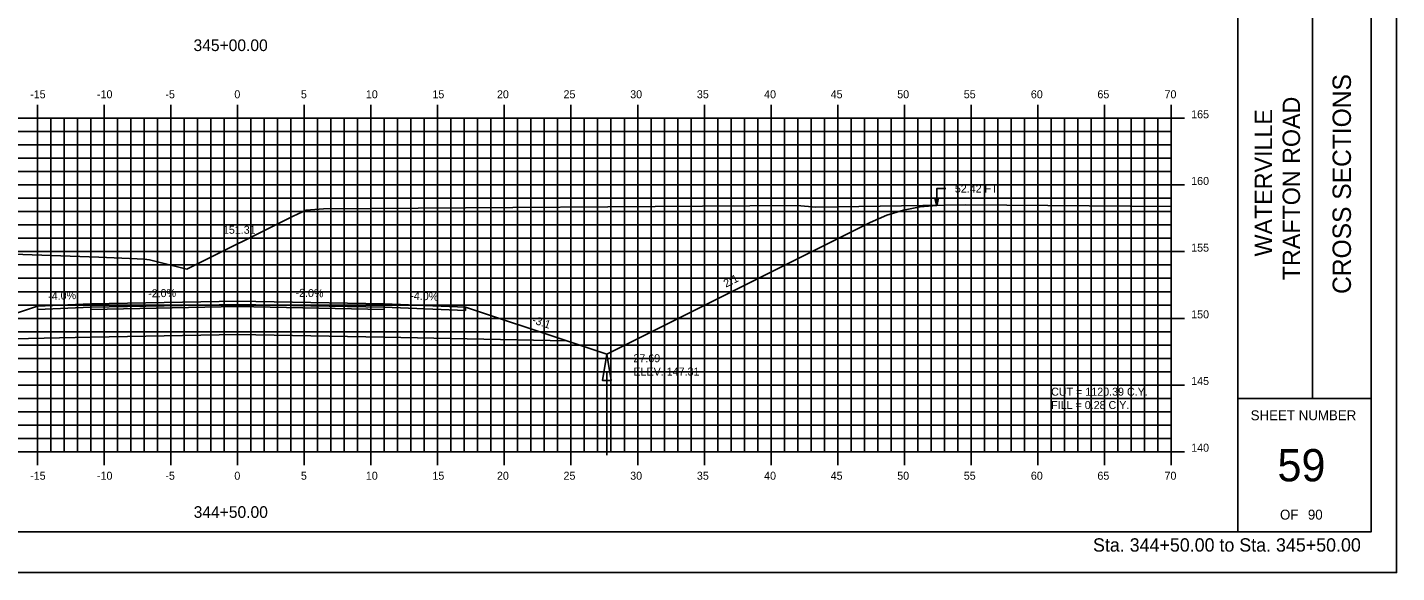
# Model space of a CAD drawing. Extents: x 1143642 to 1143812, y 608981 to 609091.
# Drawn here: x 1143709.1 to 1143811.7, y 608981.3 to 609022.2 of the extents above; entities that cross this region are included whole.
import ezdxf

# ---------------------------------------------------------------- set-up
doc = ezdxf.new("R2010")
doc.units = 0
for name, color, linetype in [('ANNOTATION', 7, 'Continuous'), ('BORDER', 7, 'Continuous'), ('D_Drainage_Ditch_Line', 7, 'Continuous'), ('D_Roadway_Centerline', 7, 'Continuous'), ('D_Roadway_Centerline_Text', 7, 'Continuous'), ('D_Roadway_Edge_Shoulder', 7, 'Continuous'), ('D_Roadway_Edge_TW', 7, 'Continuous'), ('D_Roadway_Pavement', 7, 'Continuous'), ('D_Roadway_SlopeLines', 7, 'Continuous'), ('D_Roadway_SubGrade', 7, 'Continuous'), ('D_Text_Standard', 7, 'Continuous'), ('H_V ANNOTATION', 7, 'Continuous'), ('HIGHWAY_TITLE', 7, 'Continuous'), ('MAJOR', 7, 'Continuous'), ('MINOR', 7, 'Continuous'), ('PLOT BOUNDARY', 7, 'Continuous'), ('S_Roadway_Centerline', 7, 'Continuous')]:
    doc.layers.add(name, color=color, linetype=linetype)

msp = doc.modelspace()

# ---------------------------------------------------------------- linework, layer by layer
msp.add_lwpolyline([(1143684.25, 609004.24), (1143685.5, 609004), (1143686.75, 609003.65), (1143688, 609003.19), (1143689.25, 609002.62), (1143699.11, 608997.69), (1143702.11, 608998.69), (1143709.84, 609001.26), (1143709.84, 609001.26), (1143713.84, 609001.42), (1143724.84, 609001.64), (1143735.84, 609001.42), (1143741.93, 609001.18), (1143749.52, 608998.65), (1143752.52, 608997.65), (1143772.26, 609007.52), (1143773.51, 609008.07), (1143774.76, 609008.46), (1143776.01, 609008.71), (1143777.26, 609008.8)])
at = {"layer": 'BORDER'}
for p, q in [((1143799.84, 608984.34), (1143799.84, 609089.34)), ((1143805.43, 608994.34), (1143805.43, 609029.34)), ((1143799.84, 608994.34), (1143809.84, 608994.34))]:
    msp.add_line(p, q, dxfattribs=at)
msp.add_lwpolyline([(1143649.84, 608984.34), (1143809.84, 608984.34), (1143809.84, 609089.34), (1143649.84, 609089.34)], close=True, dxfattribs=at)
at = {"layer": 'D_Drainage_Ditch_Line'}
msp.add_line((1143752.52, 608996.34), (1143752.52, 608990.09), dxfattribs=at)
msp.add_lwpolyline([(1143752.85, 608995.68), (1143752.2, 608995.68), (1143752.52, 608997.65)], close=True, dxfattribs=at)
at = {"layer": 'D_Roadway_Edge_Shoulder'}
for points in [[(1143713.84, 609001.42), (1143709.84, 609001.26), (1143709.84, 609001.01), (1143713.84, 609001.17)], [(1143735.84, 609001.42), (1143741.93, 609001.18), (1143741.93, 609000.93), (1143735.84, 609001.17)]]:
    msp.add_lwpolyline(points, close=True, dxfattribs=at)
at = {"layer": 'D_Roadway_Edge_TW'}
msp.add_lwpolyline([(1143713.84, 609001.17), (1143713.84, 609001.42), (1143724.84, 609001.64), (1143735.84, 609001.42), (1143735.84, 609001.17), (1143724.84, 609001.39)], close=True, dxfattribs=at)
at = {"layer": 'D_Roadway_Pavement'}
msp.add_lwpolyline([(1143713.84, 609001.01), (1143713.84, 609001.17), (1143724.84, 609001.39), (1143735.84, 609001.17), (1143735.84, 609001.01), (1143724.84, 609001.23)], close=True, dxfattribs=at)
at = {"layer": 'D_Roadway_SlopeLines'}
for points in [[(1143752.52, 608997.65), (1143772.26, 609007.52), (1143773.51, 609008.07), (1143774.76, 609008.46), (1143776.01, 609008.71), (1143777.26, 609008.8)], [(1143749.52, 608998.65), (1143752.52, 608997.65)]]:
    msp.add_lwpolyline(points, dxfattribs=at)
at = {"layer": 'D_Roadway_SubGrade'}
for points in [[(1143713.84, 609001.01), (1143713.84, 609001.17), (1143709.84, 609001.01), (1143709.84, 609001.26), (1143709.84, 609001.26), (1143702.11, 608998.69), (1143713.84, 608998.92)], [(1143713.84, 608998.92), (1143713.84, 609001.01), (1143724.84, 609001.23), (1143735.84, 609001.01), (1143735.84, 608998.92), (1143724.84, 608999.14)], [(1143735.84, 609001.01), (1143735.84, 609001.17), (1143741.93, 609000.93), (1143741.93, 609001.18), (1143741.93, 609001.18), (1143749.52, 608998.65), (1143735.84, 608998.92)]]:
    msp.add_lwpolyline(points, close=True, dxfattribs=at)
at = {"layer": 'D_Text_Standard'}
msp.add_lwpolyline([(1143777.26, 609008.77), (1143777.26, 609010.07), (1143777.94, 609010.07)], dxfattribs=at)
msp.add_lwpolyline([(1143777.26, 609008.77), (1143777.11, 609009.35), (1143777.4, 609009.35)], close=True, dxfattribs=at)
at = {"layer": 'MAJOR'}
for p, q in [((1143709.84, 609016.34), (1143709.84, 609015.34)), ((1143714.84, 609016.34), (1143714.84, 609015.34)), ((1143719.84, 609016.34), (1143719.84, 609015.34)), ((1143724.84, 609016.34), (1143724.84, 609015.34)), ((1143729.84, 609016.34), (1143729.84, 609015.34)), ((1143734.84, 609016.34), (1143734.84, 609015.34)), ((1143739.84, 609016.34), (1143739.84, 609015.34)), ((1143744.84, 609016.34), (1143744.84, 609015.34)), ((1143749.84, 609016.34), (1143749.84, 609015.34)), ((1143754.84, 609016.34), (1143754.84, 609015.34)), ((1143759.84, 609016.34), (1143759.84, 609015.34)), ((1143764.84, 609016.34), (1143764.84, 609015.34)), ((1143769.84, 609016.34), (1143769.84, 609015.34)), ((1143774.84, 609016.34), (1143774.84, 609015.34)), ((1143779.84, 609016.34), (1143779.84, 609015.34)), ((1143784.84, 609016.34), (1143784.84, 609015.34)), ((1143789.84, 609016.34), (1143789.84, 609015.34)), ((1143794.84, 609016.34), (1143794.84, 609015.34)), ((1143654.84, 609015.34), (1143794.84, 609015.34)), ((1143654.84, 609015.34), (1143794.84, 609015.34)), ((1143709.84, 608990.34), (1143709.84, 609015.34)), ((1143714.84, 608990.34), (1143714.84, 609015.34)), ((1143719.84, 608990.34), (1143719.84, 609015.34)), ((1143724.84, 608990.34), (1143724.84, 609015.34)), ((1143729.84, 608990.34), (1143729.84, 609015.34)), ((1143734.84, 608990.34), (1143734.84, 609015.34)), ((1143739.84, 608990.34), (1143739.84, 609015.34)), ((1143744.84, 608990.34), (1143744.84, 609015.34)), ((1143749.84, 608990.34), (1143749.84, 609015.34)), ((1143754.84, 608990.34), (1143754.84, 609015.34)), ((1143759.84, 608990.34), (1143759.84, 609015.34)), ((1143764.84, 608990.34), (1143764.84, 609015.34)), ((1143769.84, 608990.34), (1143769.84, 609015.34)), ((1143774.84, 608990.34), (1143774.84, 609015.34)), ((1143779.84, 608990.34), (1143779.84, 609015.34)), ((1143784.84, 608990.34), (1143784.84, 609015.34)), ((1143789.84, 608990.34), (1143789.84, 609015.34)), ((1143795.84, 609015.34), (1143793.83, 609015.34)), ((1143794.84, 608990.34), (1143794.84, 609015.34)), ((1143794.84, 608990.34), (1143794.84, 609015.34)), ((1143654.84, 609010.34), (1143794.84, 609010.34)), ((1143795.84, 609010.34), (1143793.83, 609010.34)), ((1143654.84, 609005.34), (1143794.84, 609005.34)), ((1143795.84, 609005.34), (1143793.83, 609005.34)), ((1143654.84, 609000.34), (1143794.84, 609000.34)), ((1143795.84, 609000.34), (1143793.83, 609000.34)), ((1143654.84, 608995.34), (1143794.84, 608995.34)), ((1143795.84, 608995.34), (1143793.83, 608995.34)), ((1143654.84, 608990.34), (1143794.84, 608990.34)), ((1143654.84, 608990.34), (1143794.84, 608990.34)), ((1143709.84, 608989.33), (1143709.84, 608990.34)), ((1143714.84, 608989.33), (1143714.84, 608990.34)), ((1143719.84, 608989.33), (1143719.84, 608990.34)), ((1143724.84, 608989.33), (1143724.84, 608990.34)), ((1143729.84, 608989.33), (1143729.84, 608990.34)), ((1143734.84, 608989.33), (1143734.84, 608990.34)), ((1143739.84, 608989.33), (1143739.84, 608990.34)), ((1143744.84, 608989.33), (1143744.84, 608990.34)), ((1143749.84, 608989.33), (1143749.84, 608990.34)), ((1143754.84, 608989.33), (1143754.84, 608990.34)), ((1143759.84, 608989.33), (1143759.84, 608990.34)), ((1143764.84, 608989.33), (1143764.84, 608990.34)), ((1143769.84, 608989.33), (1143769.84, 608990.34)), ((1143774.84, 608989.33), (1143774.84, 608990.34)), ((1143779.84, 608989.33), (1143779.84, 608990.34)), ((1143784.84, 608989.33), (1143784.84, 608990.34)), ((1143789.84, 608989.33), (1143789.84, 608990.34)), ((1143795.84, 608990.34), (1143793.83, 608990.34)), ((1143794.84, 608989.33), (1143794.84, 608990.34))]:
    msp.add_line(p, q, dxfattribs=at)
at = {"layer": 'MINOR'}
for p, q in [((1143710.84, 608990.34), (1143710.84, 609015.34)), ((1143711.84, 608990.34), (1143711.84, 609015.34)), ((1143712.84, 608990.34), (1143712.84, 609015.34)), ((1143713.84, 608990.34), (1143713.84, 609015.34)), ((1143715.84, 608990.34), (1143715.84, 609015.34)), ((1143716.84, 608990.34), (1143716.84, 609015.34)), ((1143717.84, 608990.34), (1143717.84, 609015.34)), ((1143718.84, 608990.34), (1143718.84, 609015.34)), ((1143720.84, 608990.34), (1143720.84, 609015.34)), ((1143721.84, 608990.34), (1143721.84, 609015.34)), ((1143722.84, 608990.34), (1143722.84, 609015.34)), ((1143723.84, 608990.34), (1143723.84, 609015.34)), ((1143725.84, 608990.34), (1143725.84, 609015.34)), ((1143726.84, 608990.34), (1143726.84, 609015.34)), ((1143727.84, 608990.34), (1143727.84, 609015.34)), ((1143728.84, 608990.34), (1143728.84, 609015.34)), ((1143730.84, 608990.34), (1143730.84, 609015.34)), ((1143731.84, 608990.34), (1143731.84, 609015.34)), ((1143732.84, 608990.34), (1143732.84, 609015.34)), ((1143733.84, 608990.34), (1143733.84, 609015.34)), ((1143735.84, 608990.34), (1143735.84, 609015.34)), ((1143736.84, 608990.34), (1143736.84, 609015.34)), ((1143737.84, 608990.34), (1143737.84, 609015.34)), ((1143738.84, 608990.34), (1143738.84, 609015.34)), ((1143740.84, 608990.34), (1143740.84, 609015.34)), ((1143741.84, 608990.34), (1143741.84, 609015.34)), ((1143742.84, 608990.34), (1143742.84, 609015.34)), ((1143743.84, 608990.34), (1143743.84, 609015.34)), ((1143745.84, 608990.34), (1143745.84, 609015.34)), ((1143746.84, 608990.34), (1143746.84, 609015.34)), ((1143747.84, 608990.34), (1143747.84, 609015.34)), ((1143748.84, 608990.34), (1143748.84, 609015.34)), ((1143750.84, 608990.34), (1143750.84, 609015.34)), ((1143751.84, 608990.34), (1143751.84, 609015.34)), ((1143752.84, 608990.34), (1143752.84, 609015.34)), ((1143753.84, 608990.34), (1143753.84, 609015.34)), ((1143755.84, 608990.34), (1143755.84, 609015.34)), ((1143756.84, 608990.34), (1143756.84, 609015.34)), ((1143757.84, 608990.34), (1143757.84, 609015.34)), ((1143758.84, 608990.34), (1143758.84, 609015.34)), ((1143760.84, 608990.34), (1143760.84, 609015.34)), ((1143761.84, 608990.34), (1143761.84, 609015.34)), ((1143762.84, 608990.34), (1143762.84, 609015.34)), ((1143763.84, 608990.34), (1143763.84, 609015.34)), ((1143765.84, 608990.34), (1143765.84, 609015.34)), ((1143766.84, 608990.34), (1143766.84, 609015.34)), ((1143767.84, 608990.34), (1143767.84, 609015.34)), ((1143768.84, 608990.34), (1143768.84, 609015.34)), ((1143770.84, 608990.34), (1143770.84, 609015.34)), ((1143771.84, 608990.34), (1143771.84, 609015.34)), ((1143772.84, 608990.34), (1143772.84, 609015.34)), ((1143773.84, 608990.34), (1143773.84, 609015.34)), ((1143775.84, 608990.34), (1143775.84, 609015.34)), ((1143776.84, 608990.34), (1143776.84, 609015.34)), ((1143777.84, 608990.34), (1143777.84, 609015.34)), ((1143778.84, 608990.34), (1143778.84, 609015.34)), ((1143780.84, 608990.34), (1143780.84, 609015.34)), ((1143781.84, 608990.34), (1143781.84, 609015.34)), ((1143782.84, 608990.34), (1143782.84, 609015.34)), ((1143783.84, 608990.34), (1143783.84, 609015.34)), ((1143785.84, 608990.34), (1143785.84, 609015.34)), ((1143786.84, 608990.34), (1143786.84, 609015.34)), ((1143787.84, 608990.34), (1143787.84, 609015.34)), ((1143788.84, 608990.34), (1143788.84, 609015.34)), ((1143790.84, 608990.34), (1143790.84, 609015.34)), ((1143791.84, 608990.34), (1143791.84, 609015.34)), ((1143792.84, 608990.34), (1143792.84, 609015.34)), ((1143793.84, 608990.34), (1143793.84, 609015.34)), ((1143654.84, 609014.34), (1143794.84, 609014.34)), ((1143794.84, 609014.34), (1143793.83, 609014.34)), ((1143654.84, 609013.34), (1143794.84, 609013.34)), ((1143794.84, 609013.34), (1143793.83, 609013.34)), ((1143654.84, 609012.34), (1143794.84, 609012.34)), ((1143794.84, 609012.34), (1143793.83, 609012.34)), ((1143654.84, 609011.34), (1143794.84, 609011.34)), ((1143794.84, 609011.34), (1143793.83, 609011.34)), ((1143654.84, 609009.34), (1143794.84, 609009.34)), ((1143794.84, 609009.34), (1143793.83, 609009.34)), ((1143654.84, 609008.34), (1143794.84, 609008.34)), ((1143654.84, 609007.34), (1143794.84, 609007.34)), ((1143794.84, 609008.34), (1143793.83, 609008.34)), ((1143794.84, 609007.34), (1143793.83, 609007.34)), ((1143654.84, 609006.34), (1143794.84, 609006.34)), ((1143794.84, 609006.34), (1143793.83, 609006.34)), ((1143654.84, 609004.34), (1143794.84, 609004.34)), ((1143794.84, 609004.34), (1143793.83, 609004.34)), ((1143654.84, 609003.34), (1143794.84, 609003.34)), ((1143794.84, 609003.34), (1143793.83, 609003.34)), ((1143654.84, 609002.34), (1143794.84, 609002.34)), ((1143794.84, 609002.34), (1143793.83, 609002.34)), ((1143654.84, 609001.34), (1143794.84, 609001.34)), ((1143794.84, 609001.34), (1143793.83, 609001.34)), ((1143654.84, 608999.34), (1143794.84, 608999.34)), ((1143794.84, 608999.34), (1143793.83, 608999.34)), ((1143654.84, 608998.34), (1143794.84, 608998.34)), ((1143794.84, 608998.34), (1143793.83, 608998.34)), ((1143654.84, 608997.34), (1143794.84, 608997.34)), ((1143794.84, 608997.34), (1143793.83, 608997.34)), ((1143654.84, 608996.34), (1143794.84, 608996.34)), ((1143794.84, 608996.34), (1143793.83, 608996.34)), ((1143654.84, 608994.34), (1143794.84, 608994.34)), ((1143794.84, 608994.34), (1143793.83, 608994.34)), ((1143654.84, 608993.34), (1143794.84, 608993.34)), ((1143794.84, 608993.34), (1143793.83, 608993.34)), ((1143654.84, 608992.34), (1143794.84, 608992.34)), ((1143794.84, 608992.34), (1143793.83, 608992.34)), ((1143654.84, 608991.34), (1143794.84, 608991.34)), ((1143794.84, 608991.34), (1143793.83, 608991.34))]:
    msp.add_line(p, q, dxfattribs=at)
at = {"layer": 'PLOT BOUNDARY'}
msp.add_lwpolyline([(1143641.74, 608981.28), (1143811.74, 608981.28), (1143811.74, 609091.28), (1143641.74, 609091.28)], close=True, dxfattribs=at)
at = {"layer": 'S_Roadway_Centerline'}
msp.add_lwpolyline([(1143703.71, 609005.3), (1143714.44, 609004.93), (1143717.89, 609004.77), (1143718.03, 609004.76), (1143718.24, 609004.72), (1143721.04, 609004.03), (1143729.02, 609007.99), (1143729.98, 609008.44), (1143731.29, 609008.54), (1143766.8, 609008.79), (1143768.2, 609008.67), (1143779.45, 609008.84), (1143794.84, 609008.73)], dxfattribs=at)

# ---------------------------------------------------------------- texts
at = {"layer": 'ANNOTATION'}
for s, rotation, p in [('2:1', 26.5651, (1143761.46, 609002.64)), ('-4.0%', 2.2906, (1143710.65, 609001.7)), ('-2.0%', 1.1458, (1143718.14, 609001.91)), ('-2.0%', 358.8542, (1143729.18, 609001.96)), ('-4.0%', 357.7094, (1143737.78, 609001.75)), ('-3:1', 341.5652, (1143746.88, 608999.99))]:
    msp.add_text(s, height=0.6, rotation=rotation, dxfattribs=at).set_placement(p)
at = {"layer": 'BORDER'}
msp.add_text('CROSS SECTIONS', height=1.3779, rotation=90, dxfattribs=at).set_placement((1143808.32, 609002.17))
for s, height, p in [('SHEET NUMBER', 0.7453, (1143800.8, 608992.7)), ('59', 2.419, (1143802.81, 608988.12)), ('OF', 0.745, (1143803, 608985.25)), ('90', 0.745, (1143805.09, 608985.25))]:
    msp.add_text(s, height=height, dxfattribs=at).set_placement(p)
at = {"layer": 'D_Roadway_Centerline'}
for s, p in [('C', (1143724.83, 609001.64)), ('L', (1143724.84, 609001.64))]:
    msp.add_text(s, height=0.0146, dxfattribs=at).set_placement(p)
at = {"layer": 'D_Roadway_Centerline_Text'}
msp.add_text('151.31', height=0.6, dxfattribs=at).set_placement((1143723.74, 609006.68))
at = {"layer": 'D_Text_Standard'}
for s, p in [('52.42 FT', (1143778.62, 609009.77)), ('27.69', (1143754.52, 608997.05)), ('ELEV. 147.31', (1143754.52, 608996.05)), ('CUT = 1120.39 C.Y.', (1143785.84, 608994.54)), ('FILL = 0.28 C.Y.', (1143785.84, 608993.54))]:
    msp.add_text(s, height=0.6, dxfattribs=at).set_placement(p)
at = {"layer": 'H_V ANNOTATION'}
for s, height, p in [('345+00.00', 0.875, (1143721.54, 609020.38)), ('-15', 0.6, (1143709.29, 609016.84)), ('-10', 0.6, (1143714.3, 609016.84)), ('-5', 0.6, (1143719.43, 609016.84)), ('0', 0.6, (1143724.6, 609016.84)), ('5', 0.6, (1143729.59, 609016.84)), ('10', 0.6, (1143734.46, 609016.84)), ('15', 0.6, (1143739.45, 609016.84)), ('20', 0.6, (1143744.29, 609016.84)), ('25', 0.6, (1143749.28, 609016.84)), ('30', 0.6, (1143754.28, 609016.84)), ('35', 0.6, (1143759.28, 609016.84)), ('40', 0.6, (1143764.32, 609016.84)), ('45', 0.6, (1143769.31, 609016.84)), ('50', 0.6, (1143774.3, 609016.84)), ('55', 0.6, (1143779.29, 609016.84)), ('60', 0.6, (1143784.32, 609016.84)), ('65', 0.6, (1143789.31, 609016.84)), ('70', 0.6, (1143794.34, 609016.84)), ('165', 0.6, (1143796.34, 609015.34)), ('160', 0.6, (1143796.34, 609010.34)), ('155', 0.6, (1143796.34, 609005.34)), ('150', 0.6, (1143796.34, 609000.34)), ('145', 0.6, (1143796.34, 608995.34)), ('140', 0.6, (1143796.34, 608990.34)), ('-15', 0.6, (1143709.29, 608988.24)), ('-10', 0.6, (1143714.3, 608988.24)), ('-5', 0.6, (1143719.43, 608988.24)), ('0', 0.6, (1143724.6, 608988.24)), ('5', 0.6, (1143729.59, 608988.24)), ('10', 0.6, (1143734.46, 608988.24)), ('15', 0.6, (1143739.45, 608988.24)), ('20', 0.6, (1143744.29, 608988.24)), ('25', 0.6, (1143749.28, 608988.24)), ('30', 0.6, (1143754.28, 608988.24)), ('35', 0.6, (1143759.28, 608988.24)), ('40', 0.6, (1143764.32, 608988.24)), ('45', 0.6, (1143769.31, 608988.24)), ('50', 0.6, (1143774.3, 608988.24)), ('55', 0.6, (1143779.29, 608988.24)), ('60', 0.6, (1143784.32, 608988.24)), ('65', 0.6, (1143789.31, 608988.24)), ('70', 0.6, (1143794.34, 608988.24)), ('344+50.00', 0.875, (1143721.55, 608985.38)), ('Sta. 344+50.00 to Sta. 345+50.00', 1.0002, (1143788.98, 608982.85))]:
    msp.add_text(s, height=height, dxfattribs=at).set_placement(p)
at = {"layer": 'HIGHWAY_TITLE'}
for s, height, p in [('TRAFTON ROAD', 1.3043, (1143804.5, 609003.2)), ('WATERVILLE', 1.304, (1143802.41, 609004.98))]:
    msp.add_text(s, height=height, rotation=90, dxfattribs=at).set_placement(p)

doc.saveas('drawing.dxf')
